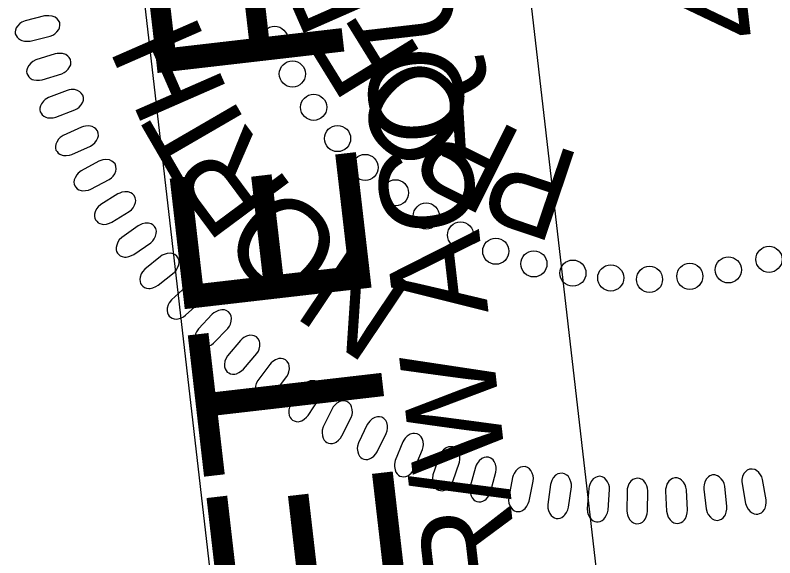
# Model space of a CAD drawing. Extents: x 477607 to 479438, y 495543 to 499482.
# Drawn here: x 477701.76 to 477748.3, y 497315.98 to 497349.21 of the extents above; entities that cross this region are included whole.
import ezdxf

# ---------------------------------------------------------------- set-up
doc = ezdxf.new("R2010")
doc.units = 0
doc.layers.add('Sheet PE Seal Cell', color=7, linetype='Continuous')
doc.layers.add('Sheet Sticker Incomplete CELL', color=7, linetype='Continuous')

msp = doc.modelspace()

# ---------------------------------------------------------------- linework, layer by layer
at = {"layer": 'Sheet PE Seal Cell'}
for points in [[(477703.561, 497349.161), (477702.37, 497348.869), (477702.165, 497348.781), (477702.042, 497348.697), (477701.904, 497348.547), (477701.821, 497348.427), (477701.77, 497348.299), (477701.756, 497348.188), (477701.763, 497348.074), (477701.81, 497347.97), (477701.867, 497347.861), (477701.95, 497347.773), (477702.072, 497347.695), (477702.163, 497347.656), (477702.325, 497347.626), (477702.513, 497347.611), (477702.674, 497347.627), (477703.896, 497347.919), (477704.055, 497347.981), (477704.18, 497348.058), (477704.314, 497348.183), (477704.423, 497348.325), (477704.477, 497348.438), (477704.498, 497348.605), (477704.482, 497348.755), (477704.408, 497348.891), (477704.334, 497348.981), (477704.207, 497349.08), (477704.014, 497349.156), (477703.824, 497349.179), (477703.691, 497349.177)], [(477704.199, 497346.837), (477703.029, 497346.472), (477702.831, 497346.37), (477702.713, 497346.279), (477702.584, 497346.121), (477702.509, 497345.996), (477702.466, 497345.865), (477702.459, 497345.753), (477702.473, 497345.64), (477702.526, 497345.539), (477702.59, 497345.434), (477702.678, 497345.352), (477702.805, 497345.281), (477702.899, 497345.248), (477703.062, 497345.229), (477703.251, 497345.225), (477703.41, 497345.251), (477704.611, 497345.619), (477704.767, 497345.691), (477704.887, 497345.775), (477705.012, 497345.909), (477705.112, 497346.058), (477705.159, 497346.174), (477705.169, 497346.342), (477705.144, 497346.49), (477705.061, 497346.621), (477704.982, 497346.706), (477704.849, 497346.798), (477704.652, 497346.861), (477704.46, 497346.872), (477704.328, 497346.861)], [(477704.933, 497344.601), (477703.787, 497344.163), (477703.596, 497344.049), (477703.484, 497343.95), (477703.366, 497343.785), (477703.298, 497343.655), (477703.264, 497343.522), (477703.263, 497343.409), (477703.285, 497343.298), (477703.343, 497343.2), (477703.415, 497343.099), (477703.508, 497343.023), (477703.639, 497342.961), (477703.734, 497342.933), (477703.898, 497342.924), (477704.087, 497342.933), (477704.244, 497342.968), (477705.42, 497343.411), (477705.571, 497343.493), (477705.685, 497343.585), (477705.802, 497343.726), (477705.892, 497343.88), (477705.932, 497343.999), (477705.932, 497344.168), (477705.897, 497344.314), (477705.806, 497344.44), (477705.722, 497344.52), (477705.583, 497344.602), (477705.382, 497344.653), (477705.19, 497344.652), (477705.059, 497344.634)], [(477705.817, 497342.354), (477704.701, 497341.844), (477704.517, 497341.719), (477704.412, 497341.614), (477704.304, 497341.441), (477704.244, 497341.307), (477704.218, 497341.172), (477704.226, 497341.06), (477704.254, 497340.95), (477704.318, 497340.856), (477704.396, 497340.76), (477704.493, 497340.69), (477704.628, 497340.636), (477704.725, 497340.615), (477704.889, 497340.615), (477705.077, 497340.636), (477705.232, 497340.682), (477706.378, 497341.197), (477706.523, 497341.288), (477706.631, 497341.387), (477706.739, 497341.535), (477706.819, 497341.695), (477706.851, 497341.816), (477706.841, 497341.984), (477706.797, 497342.128), (477706.698, 497342.248), (477706.609, 497342.322), (477706.466, 497342.396), (477706.262, 497342.435), (477706.071, 497342.421), (477705.94, 497342.395)], [(477706.88, 497340.261), (477705.798, 497339.682), (477705.622, 497339.546), (477705.524, 497339.434), (477705.427, 497339.255), (477705.376, 497339.118), (477705.359, 497338.981), (477705.373, 497338.87), (477705.409, 497338.762), (477705.479, 497338.672), (477705.562, 497338.581), (477705.664, 497338.517), (477705.801, 497338.471), (477705.9, 497338.457), (477706.064, 497338.468), (477706.25, 497338.5), (477706.401, 497338.555), (477707.513, 497339.142), (477707.651, 497339.242), (477707.753, 497339.347), (477707.852, 497339.502), (477707.922, 497339.666), (477707.947, 497339.789), (477707.925, 497339.956), (477707.872, 497340.098), (477707.766, 497340.21), (477707.673, 497340.279), (477707.525, 497340.344), (477707.319, 497340.37), (477707.129, 497340.344), (477707.001, 497340.309)], [(477708.049, 497338.265), (477707.006, 497337.619), (477706.839, 497337.472), (477706.748, 497337.354), (477706.662, 497337.17), (477706.621, 497337.029), (477706.612, 497336.892), (477706.633, 497336.781), (477706.675, 497336.676), (477706.751, 497336.591), (477706.839, 497336.505), (477706.945, 497336.447), (477707.085, 497336.411), (477707.184, 497336.402), (477707.347, 497336.423), (477707.531, 497336.467), (477707.679, 497336.532), (477708.75, 497337.187), (477708.883, 497337.296), (477708.978, 497337.407), (477709.066, 497337.568), (477709.127, 497337.737), (477709.143, 497337.861), (477709.111, 497338.026), (477709.05, 497338.164), (477708.937, 497338.269), (477708.839, 497338.332), (477708.688, 497338.388), (477708.481, 497338.401), (477708.293, 497338.363), (477708.167, 497338.32)], [(477709.295, 497336.312), (477708.294, 497335.601), (477708.137, 497335.444), (477708.053, 497335.321), (477707.98, 497335.131), (477707.946, 497334.989), (477707.946, 497334.851), (477707.974, 497334.743), (477708.023, 497334.639), (477708.104, 497334.56), (477708.198, 497334.479), (477708.307, 497334.428), (477708.449, 497334.401), (477708.549, 497334.398), (477708.71, 497334.43), (477708.891, 497334.485), (477709.034, 497334.559), (477710.063, 497335.28), (477710.188, 497335.396), (477710.276, 497335.514), (477710.354, 497335.679), (477710.403, 497335.852), (477710.412, 497335.977), (477710.37, 497336.14), (477710.3, 497336.273), (477710.181, 497336.372), (477710.08, 497336.429), (477709.925, 497336.475), (477709.717, 497336.474), (477709.532, 497336.425), (477709.409, 497336.374)], [(477710.66, 497334.438), (477709.706, 497333.667), (477709.559, 497333.5), (477709.484, 497333.372), (477709.422, 497333.178), (477709.398, 497333.033), (477709.406, 497332.896), (477709.441, 497332.789), (477709.496, 497332.69), (477709.582, 497332.614), (477709.681, 497332.541), (477709.793, 497332.497), (477709.936, 497332.478), (477710.036, 497332.482), (477710.195, 497332.524), (477710.372, 497332.59), (477710.51, 497332.673), (477711.492, 497333.457), (477711.61, 497333.581), (477711.69, 497333.704), (477711.758, 497333.874), (477711.796, 497334.049), (477711.797, 497334.175), (477711.744, 497334.334), (477711.666, 497334.463), (477711.541, 497334.555), (477711.436, 497334.604), (477711.279, 497334.641), (477711.072, 497334.627), (477710.89, 497334.566), (477710.771, 497334.508)], [(477712.235, 497332.606), (477711.332, 497331.776), (477711.195, 497331.6), (477711.127, 497331.468), (477711.078, 497331.27), (477711.064, 497331.124), (477711.081, 497330.988), (477711.122, 497330.883), (477711.183, 497330.788), (477711.274, 497330.718), (477711.376, 497330.651), (477711.491, 497330.614), (477711.636, 497330.604), (477711.735, 497330.614), (477711.891, 497330.666), (477712.063, 497330.743), (477712.196, 497330.835), (477713.127, 497331.679), (477713.236, 497331.81), (477713.309, 497331.938), (477713.366, 497332.111), (477713.393, 497332.288), (477713.386, 497332.414), (477713.324, 497332.57), (477713.237, 497332.694), (477713.107, 497332.777), (477713, 497332.82), (477712.84, 497332.847), (477712.634, 497332.82), (477712.456, 497332.748), (477712.34, 497332.682)], [(477713.83, 497330.897), (477712.981, 497330.012), (477712.856, 497329.828), (477712.796, 497329.691), (477712.76, 497329.491), (477712.754, 497329.345), (477712.78, 497329.209), (477712.828, 497329.109), (477712.895, 497329.016), (477712.99, 497328.953), (477713.097, 497328.892), (477713.213, 497328.862), (477713.358, 497328.862), (477713.456, 497328.878), (477713.609, 497328.939), (477713.776, 497329.027), (477713.903, 497329.127), (477714.779, 497330.027), (477714.88, 497330.166), (477714.944, 497330.298), (477714.99, 497330.474), (477715.006, 497330.653), (477714.991, 497330.778), (477714.919, 497330.93), (477714.825, 497331.048), (477714.689, 497331.122), (477714.58, 497331.159), (477714.419, 497331.175), (477714.216, 497331.135), (477714.043, 497331.052), (477713.931, 497330.98)], [(477715.564, 497329.297), (477714.771, 497328.361), (477714.658, 497328.169), (477714.607, 497328.029), (477714.584, 497327.827), (477714.587, 497327.681), (477714.621, 497327.547), (477714.675, 497327.449), (477714.748, 497327.361), (477714.847, 497327.304), (477714.958, 497327.25), (477715.076, 497327.228), (477715.22, 497327.236), (477715.317, 497327.258), (477715.465, 497327.329), (477715.627, 497327.428), (477715.747, 497327.534), (477716.565, 497328.489), (477716.657, 497328.633), (477716.713, 497328.769), (477716.747, 497328.948), (477716.752, 497329.128), (477716.73, 497329.252), (477716.649, 497329.398), (477716.547, 497329.51), (477716.407, 497329.576), (477716.295, 497329.606), (477716.134, 497329.612), (477715.933, 497329.56), (477715.766, 497329.466), (477715.659, 497329.387)], [(477717.353, 497327.83), (477716.621, 497326.846), (477716.52, 497326.647), (477716.479, 497326.504), (477716.467, 497326.301), (477716.48, 497326.155), (477716.522, 497326.024), (477716.582, 497325.93), (477716.661, 497325.847), (477716.762, 497325.796), (477716.876, 497325.749), (477716.996, 497325.734), (477717.139, 497325.752), (477717.235, 497325.78), (477717.379, 497325.86), (477717.533, 497325.968), (477717.647, 497326.083), (477718.403, 497327.087), (477718.486, 497327.236), (477718.533, 497327.375), (477718.556, 497327.557), (477718.55, 497327.735), (477718.52, 497327.857), (477718.429, 497327.999), (477718.321, 497328.104), (477718.177, 497328.161), (477718.064, 497328.184), (477717.902, 497328.18), (477717.705, 497328.115), (477717.544, 497328.011), (477717.443, 497327.925)], [(477719.313, 497326.432), (477718.644, 497325.404), (477718.556, 497325.199), (477718.523, 497325.054), (477718.525, 497324.851), (477718.547, 497324.706), (477718.597, 497324.578), (477718.663, 497324.488), (477718.747, 497324.41), (477718.851, 497324.365), (477718.968, 497324.325), (477719.088, 497324.318), (477719.23, 497324.345), (477719.324, 497324.379), (477719.462, 497324.468), (477719.61, 497324.586), (477719.716, 497324.707), (477720.407, 497325.756), (477720.481, 497325.911), (477720.519, 497326.052), (477720.531, 497326.235), (477720.513, 497326.413), (477720.475, 497326.533), (477720.376, 497326.668), (477720.262, 497326.766), (477720.115, 497326.815), (477720, 497326.83), (477719.839, 497326.816), (477719.647, 497326.739), (477719.492, 497326.625), (477719.396, 497326.532)], [(477721.179, 497325.112), (477720.635, 497324.013), (477720.572, 497323.799), (477720.557, 497323.651), (477720.582, 497323.449), (477720.62, 497323.308), (477720.686, 497323.187), (477720.762, 497323.105), (477720.854, 497323.037), (477720.963, 497323.005), (477721.084, 497322.98), (477721.204, 497322.986), (477721.342, 497323.03), (477721.431, 497323.075), (477721.557, 497323.179), (477721.691, 497323.314), (477721.781, 497323.447), (477722.345, 497324.57), (477722.4, 497324.732), (477722.421, 497324.877), (477722.411, 497325.06), (477722.373, 497325.234), (477722.32, 497325.349), (477722.206, 497325.472), (477722.082, 497325.556), (477721.93, 497325.587), (477721.814, 497325.588), (477721.656, 497325.556), (477721.474, 497325.457), (477721.334, 497325.325), (477721.25, 497325.222)], [(477723.327, 497324.138), (477722.793, 497323.034), (477722.731, 497322.82), (477722.716, 497322.672), (477722.743, 497322.47), (477722.783, 497322.329), (477722.849, 497322.208), (477722.926, 497322.127), (477723.019, 497322.06), (477723.129, 497322.029), (477723.249, 497322.004), (477723.369, 497322.012), (477723.507, 497322.056), (477723.596, 497322.102), (477723.722, 497322.208), (477723.853, 497322.343), (477723.943, 497322.477), (477724.497, 497323.605), (477724.551, 497323.767), (477724.572, 497323.912), (477724.56, 497324.095), (477724.52, 497324.269), (477724.468, 497324.384), (477724.352, 497324.506), (477724.226, 497324.589), (477724.075, 497324.618), (477723.959, 497324.619), (477723.801, 497324.584), (477723.62, 497324.484), (477723.481, 497324.352), (477723.397, 497324.248)], [(477725.512, 497323.078), (477725.048, 497321.942), (477724.999, 497321.725), (477724.995, 497321.576), (477725.035, 497321.376), (477725.083, 497321.238), (477725.156, 497321.122), (477725.238, 497321.046), (477725.334, 497320.984), (477725.446, 497320.961), (477725.568, 497320.943), (477725.687, 497320.959), (477725.822, 497321.011), (477725.907, 497321.063), (477726.026, 497321.176), (477726.15, 497321.319), (477726.231, 497321.459), (477726.713, 497322.619), (477726.757, 497322.784), (477726.768, 497322.93), (477726.745, 497323.112), (477726.695, 497323.284), (477726.635, 497323.394), (477726.512, 497323.509), (477726.381, 497323.584), (477726.228, 497323.603), (477726.113, 497323.597), (477725.957, 497323.553), (477725.782, 497323.441), (477725.652, 497323.301), (477725.575, 497323.192)], [(477727.749, 497322.22), (477727.357, 497321.057), (477727.322, 497320.837), (477727.327, 497320.688), (477727.379, 497320.492), (477727.436, 497320.356), (477727.517, 497320.245), (477727.603, 497320.174), (477727.703, 497320.119), (477727.816, 497320.102), (477727.939, 497320.093), (477728.057, 497320.116), (477728.188, 497320.177), (477728.27, 497320.233), (477728.382, 497320.354), (477728.496, 497320.505), (477728.569, 497320.648), (477728.977, 497321.838), (477729.01, 497322.005), (477729.011, 497322.151), (477728.978, 497322.331), (477728.916, 497322.499), (477728.85, 497322.606), (477728.72, 497322.713), (477728.585, 497322.78), (477728.43, 497322.789), (477728.315, 497322.776), (477728.163, 497322.722), (477727.995, 497322.6), (477727.875, 497322.451), (477727.805, 497322.337)], [(477729.961, 497321.529), (477729.643, 497320.345), (477729.623, 497320.123), (477729.636, 497319.974), (477729.701, 497319.781), (477729.766, 497319.65), (477729.854, 497319.544), (477729.945, 497319.479), (477730.048, 497319.43), (477730.161, 497319.421), (477730.285, 497319.419), (477730.401, 497319.448), (477730.528, 497319.518), (477730.607, 497319.579), (477730.71, 497319.707), (477730.814, 497319.865), (477730.878, 497320.013), (477731.211, 497321.224), (477731.233, 497321.393), (477731.226, 497321.54), (477731.181, 497321.717), (477731.109, 497321.881), (477731.036, 497321.984), (477730.9, 497322.083), (477730.761, 497322.14), (477730.606, 497322.141), (477730.492, 497322.119), (477730.343, 497322.057), (477730.184, 497321.924), (477730.072, 497321.767), (477730.01, 497321.65)], [(477732.237, 497320.91), (477731.994, 497319.707), (477731.987, 497319.485), (477732.01, 497319.337), (477732.086, 497319.149), (477732.16, 497319.022), (477732.254, 497318.922), (477732.348, 497318.862), (477732.455, 497318.821), (477732.568, 497318.818), (477732.692, 497318.823), (477732.806, 497318.861), (477732.928, 497318.938), (477733.003, 497319.005), (477733.099, 497319.138), (477733.192, 497319.302), (477733.246, 497319.454), (477733.503, 497320.684), (477733.514, 497320.855), (477733.498, 497321), (477733.442, 497321.175), (477733.359, 497321.333), (477733.28, 497321.432), (477733.139, 497321.521), (477732.996, 497321.57), (477732.841, 497321.56), (477732.729, 497321.532), (477732.584, 497321.46), (477732.434, 497321.318), (477732.332, 497321.155), (477732.277, 497321.034)], [(477746.292, 497320.517), (477746.508, 497319.309), (477746.584, 497319.1), (477746.66, 497318.972), (477746.801, 497318.825), (477746.915, 497318.733), (477747.04, 497318.675), (477747.15, 497318.654), (477747.264, 497318.655), (477747.37, 497318.694), (477747.483, 497318.745), (477747.576, 497318.821), (477747.661, 497318.939), (477747.706, 497319.028), (477747.745, 497319.186), (477747.773, 497319.374), (477747.767, 497319.534), (477747.552, 497320.773), (477747.5, 497320.936), (477747.431, 497321.065), (477747.315, 497321.207), (477747.18, 497321.324), (477747.071, 497321.386), (477746.905, 497321.417), (477746.755, 497321.41), (477746.614, 497321.345), (477746.52, 497321.277), (477746.413, 497321.156), (477746.325, 497320.969), (477746.29, 497320.78), (477746.284, 497320.647)], [(477734.558, 497320.469), (477734.391, 497319.253), (477734.398, 497319.031), (477734.43, 497318.885), (477734.519, 497318.702), (477734.6, 497318.58), (477734.7, 497318.485), (477734.798, 497318.432), (477734.907, 497318.396), (477735.02, 497318.401), (477735.143, 497318.414), (477735.255, 497318.459), (477735.372, 497318.544), (477735.442, 497318.615), (477735.53, 497318.754), (477735.613, 497318.924), (477735.657, 497319.078), (477735.836, 497320.322), (477735.837, 497320.493), (477735.811, 497320.638), (477735.744, 497320.808), (477735.653, 497320.961), (477735.567, 497321.054), (477735.419, 497321.135), (477735.274, 497321.175), (477735.121, 497321.156), (477735.01, 497321.12), (477734.87, 497321.039), (477734.729, 497320.888), (477734.638, 497320.719), (477734.591, 497320.594)], [(477736.897, 497320.224), (477736.807, 497319), (477736.828, 497318.779), (477736.869, 497318.635), (477736.969, 497318.458), (477737.057, 497318.341), (477737.164, 497318.253), (477737.265, 497318.206), (477737.375, 497318.177), (477737.488, 497318.19), (477737.61, 497318.21), (477737.718, 497318.262), (477737.83, 497318.354), (477737.896, 497318.429), (477737.974, 497318.573), (477738.047, 497318.748), (477738.081, 497318.905), (477738.182, 497320.159), (477738.172, 497320.329), (477738.137, 497320.472), (477738.06, 497320.637), (477737.958, 497320.785), (477737.867, 497320.871), (477737.715, 497320.943), (477737.567, 497320.974), (477737.415, 497320.945), (477737.307, 497320.903), (477737.173, 497320.813), (477737.041, 497320.653), (477736.961, 497320.478), (477736.921, 497320.351)], [(477739.245, 497320.071), (477739.231, 497318.844), (477739.266, 497318.625), (477739.316, 497318.484), (477739.427, 497318.313), (477739.522, 497318.202), (477739.634, 497318.121), (477739.738, 497318.08), (477739.85, 497318.059), (477739.962, 497318.078), (477740.082, 497318.107), (477740.187, 497318.165), (477740.293, 497318.264), (477740.354, 497318.343), (477740.423, 497318.492), (477740.485, 497318.67), (477740.509, 497318.83), (477740.53, 497320.086), (477740.51, 497320.256), (477740.466, 497320.396), (477740.379, 497320.556), (477740.268, 497320.697), (477740.171, 497320.778), (477740.015, 497320.84), (477739.866, 497320.862), (477739.716, 497320.823), (477739.611, 497320.775), (477739.483, 497320.677), (477739.362, 497320.508), (477739.292, 497320.329), (477739.261, 497320.2)], [(477741.606, 497320.055), (477741.669, 497318.83), (477741.718, 497318.612), (477741.777, 497318.475), (477741.898, 497318.312), (477742.001, 497318.207), (477742.117, 497318.134), (477742.223, 497318.099), (477742.336, 497318.085), (477742.447, 497318.111), (477742.565, 497318.147), (477742.667, 497318.212), (477742.766, 497318.317), (477742.821, 497318.4), (477742.881, 497318.553), (477742.932, 497318.735), (477742.946, 497318.895), (477742.888, 497320.151), (477742.857, 497320.319), (477742.805, 497320.456), (477742.707, 497320.611), (477742.588, 497320.744), (477742.487, 497320.819), (477742.327, 497320.871), (477742.177, 497320.883), (477742.03, 497320.835), (477741.927, 497320.78), (477741.806, 497320.674), (477741.695, 497320.499), (477741.637, 497320.316), (477741.614, 497320.185)], [(477743.956, 497320.195), (477744.096, 497318.976), (477744.159, 497318.763), (477744.226, 497318.629), (477744.357, 497318.474), (477744.466, 497318.376), (477744.587, 497318.31), (477744.695, 497318.282), (477744.809, 497318.275), (477744.918, 497318.308), (477745.033, 497318.351), (477745.13, 497318.422), (477745.223, 497318.534), (477745.273, 497318.619), (477745.323, 497318.776), (477745.362, 497318.961), (477745.366, 497319.122), (477745.23, 497320.372), (477745.189, 497320.537), (477745.128, 497320.671), (477745.02, 497320.819), (477744.893, 497320.945), (477744.787, 497321.013), (477744.625, 497321.055), (477744.474, 497321.057), (477744.33, 497321), (477744.232, 497320.939), (477744.116, 497320.826), (477744.017, 497320.644), (477743.971, 497320.458), (477743.956, 497320.325)]]:
    msp.add_lwpolyline(points, close=True, dxfattribs=at)
for centre in [(477717.656, 497347.73), (477718.742, 497345.611), (477720.045, 497343.572), (477721.508, 497341.656), (477723.196, 497339.886), (477725.058, 497338.337), (477726.946, 497336.911), (477729.044, 497335.75), (477731.204, 497334.756), (477733.538, 497333.982), (477747.947, 497334.26), (477745.455, 497333.613), (477735.929, 497333.415), (477738.249, 497333.121), (477740.625, 497333.034), (477743.094, 497333.221)]:
    msp.add_circle(centre, 0.801, dxfattribs=at)
at = {"layer": 'Sheet Sticker Incomplete CELL'}
msp.add_lwpolyline([(477746.678, 497234.443), (477723.333, 497231.751), (477706.495, 497377.784), (477729.84, 497380.475)], close=True, dxfattribs=at)

# ---------------------------------------------------------------- texts
at = {"layer": 'Sheet PE Seal Cell'}
for s, height, rotation, p in [('46155', 6.2363, 96.5586, (477748.245, 497348.026)), ('E', 5.669, 113.7459, (477724.872, 497349.826)), ('H', 5.669, 113.633, (477714.853, 497344.446)), ('F', 5.669, 121.6857, (477726.788, 497346.634)), ('O', 5.669, 137.5653, (477730.33, 497343.321)), ('R', 5.669, 153.4449, (477733.056, 497341.91)), ('T', 5.669, 120.1224, (477716.618, 497341.45)), ('R', 5.669, 126.6117, (477718.893, 497338.47)), ('P', 5.669, 161.3847, (477736.589, 497340.62)), ('O', 5.669, 139.5905, (477722.299, 497335.364)), ('N', 5.669, 146.0798, (477726.413, 497332.47))]:
    msp.add_text(s, height=height, rotation=rotation, dxfattribs=at).set_placement(p)
at = {"layer": 'Sheet Sticker Incomplete CELL'}
for s, height, p in [('INCOMPLETE PLANS', 11.52, (477734.03, 497241.994)), ('DO NOT USE FOR R/W ACQUISITION', 5.76, (477740.562, 497246.018))]:
    msp.add_text(s, height=height, rotation=96.5773, dxfattribs=at).set_placement(p)

doc.saveas('drawing.dxf')
